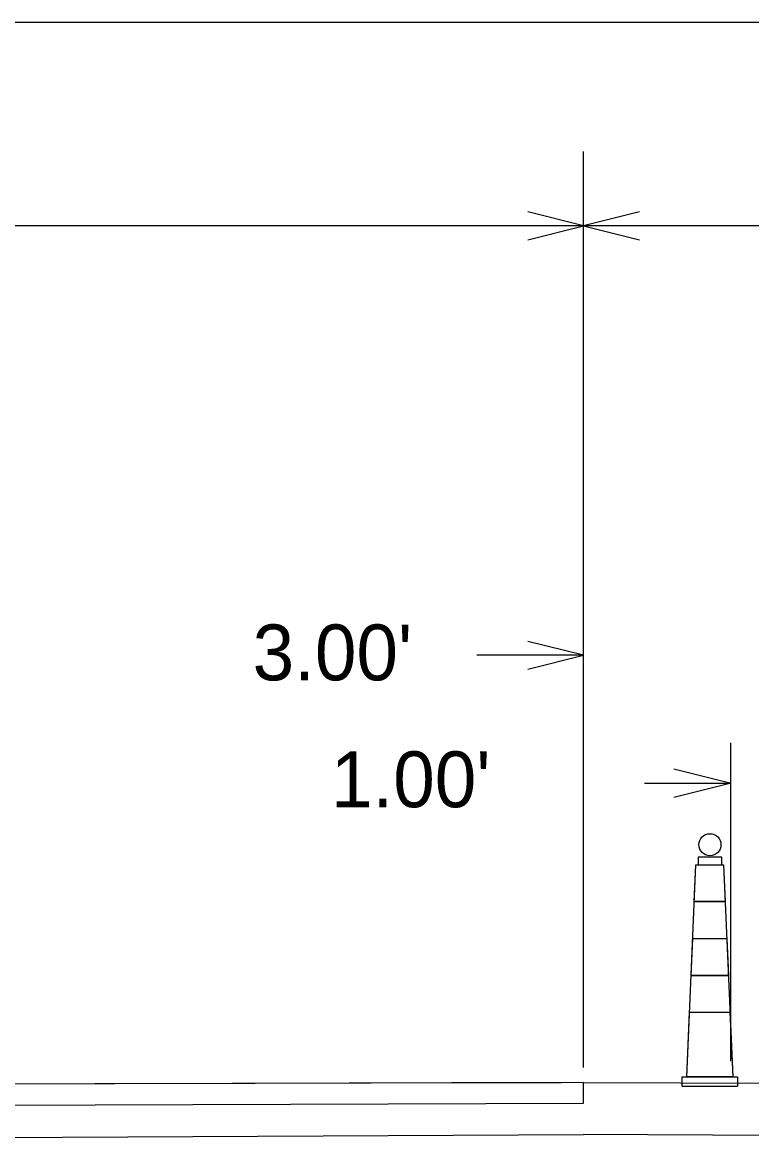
# Model space of a CAD drawing. Extents: x 8771 to 81668, y 6145 to 11018.
# Drawn here: x 15020.9 to 15317.4, y 8463.9 to 8919 of the extents above; entities that cross this region are included whole.
import ezdxf

# ---------------------------------------------------------------- set-up
doc = ezdxf.new("R2010")
doc.units = 0
for name, color, linetype in [('dsnCellElements', 7, 'Continuous'), ('Level 8', 7, 'Continuous'), ('ShtPlotIdentification', 7, 'Continuous')]:
    doc.layers.add(name, color=color, linetype=linetype)

msp = doc.modelspace()

# ---------------------------------------------------------------- linework, layer by layer
at = {"layer": 'dsnCellElements'}
for p, q in [((15873.4, 8919.02), (14624.81, 8919.02)), ((15249.1, 8494.11), (15249.1, 8866.47)), ((15249.1, 8836.31), (14624.81, 8836.31)), ((15873.4, 8836.31), (15249.1, 8836.31)), ((15249.1, 8661.66), (15205.66, 8661.66)), ((15308.92, 8496.66), (15308.92, 8626.09)), ((15273.81, 8609.63), (15308.5, 8609.63)), ((14683.59, 8463.92), (15249.1, 8466.84)), ((15814.62, 8463.92), (15249.1, 8466.84))]:
    msp.add_line(p, q, dxfattribs=at)
for points in [[(15226.4, 8830.63), (15249.1, 8836.31), (15226.4, 8841.98)], [(15271.81, 8841.98), (15249.1, 8836.31), (15271.81, 8830.63)], [(15226.4, 8655.98), (15249.1, 8661.66), (15226.4, 8667.34)], [(15285.79, 8603.95), (15308.5, 8609.63), (15285.79, 8615.31)]]:
    msp.add_lwpolyline(points, dxfattribs=at)
at = {"layer": 'Level 8'}
for p, q in [((15291, 8490.28), (15294.75, 8576.53)), ((15294.1, 8561.53), (15294.75, 8576.53)), ((15294.75, 8576.53), (15306, 8576.53)), ((15294.75, 8576.53), (15306, 8576.53)), ((15306, 8576.53), (15309.75, 8490.28)), ((15306, 8576.53), (15306.65, 8561.53)), ((15294.1, 8561.53), (15306.65, 8561.53)), ((15306.65, 8561.53), (15294.1, 8561.53)), ((15292.79, 8531.53), (15293.44, 8546.53)), ((15293.44, 8546.53), (15307.3, 8546.53)), ((15293.44, 8546.53), (15307.3, 8546.53)), ((15307.3, 8546.53), (15307.95, 8531.53)), ((15292.79, 8531.53), (15307.95, 8531.53)), ((15307.95, 8531.53), (15292.79, 8531.53)), ((15291, 8490.28), (15292.14, 8516.53)), ((15292.14, 8516.53), (15308.61, 8516.53)), ((15292.14, 8516.53), (15308.61, 8516.53)), ((15308.61, 8516.53), (15309.75, 8490.28)), ((15289.12, 8490.28), (15311.62, 8490.28)), ((15289.12, 8486.53), (15289.12, 8490.28)), ((15309.75, 8490.28), (15291, 8490.28)), ((15311.62, 8490.28), (15311.62, 8486.53)), ((15289.12, 8486.53), (15311.62, 8486.53))]:
    msp.add_line(p, q, dxfattribs=at)
msp.add_lwpolyline([(15305.25, 8579.53), (15295.65, 8579.53), (15295.65, 8576.53), (15305.25, 8576.53)], close=True, dxfattribs=at)
msp.add_circle((15300.45, 8584.63), 4.5, dxfattribs=at)
at = {"layer": 'ShtPlotIdentification'}
for p, q in [((15249.1, 8487.95), (14624.81, 8486.32)), ((15249.1, 8487.95), (15873.4, 8486.32)), ((15249.1, 8479.53), (15249.1, 8484.14)), ((14820.79, 8478.23), (15249.1, 8479.53))]:
    msp.add_line(p, q, dxfattribs=at)
msp.add_lwpolyline([(15249.1, 8484.14), (15249.1, 8487.95), (15239.94, 8487.87), (15221.42, 8487.83), (15195.42, 8487.76), (15162.68, 8487.68), (15115.51, 8487.57), (15050.26, 8487.41), (15015.81, 8487.33), (14818.62, 8486.85)], dxfattribs=at)

# ---------------------------------------------------------------- texts
at = {"layer": 'dsnCellElements'}
for s, p in [("3.00'", (15114.5, 8651.48)), ("1.00'", (15146.35, 8599.88))]:
    msp.add_text(s, height=22.709, dxfattribs=at).set_placement(p)

doc.saveas('drawing.dxf')
